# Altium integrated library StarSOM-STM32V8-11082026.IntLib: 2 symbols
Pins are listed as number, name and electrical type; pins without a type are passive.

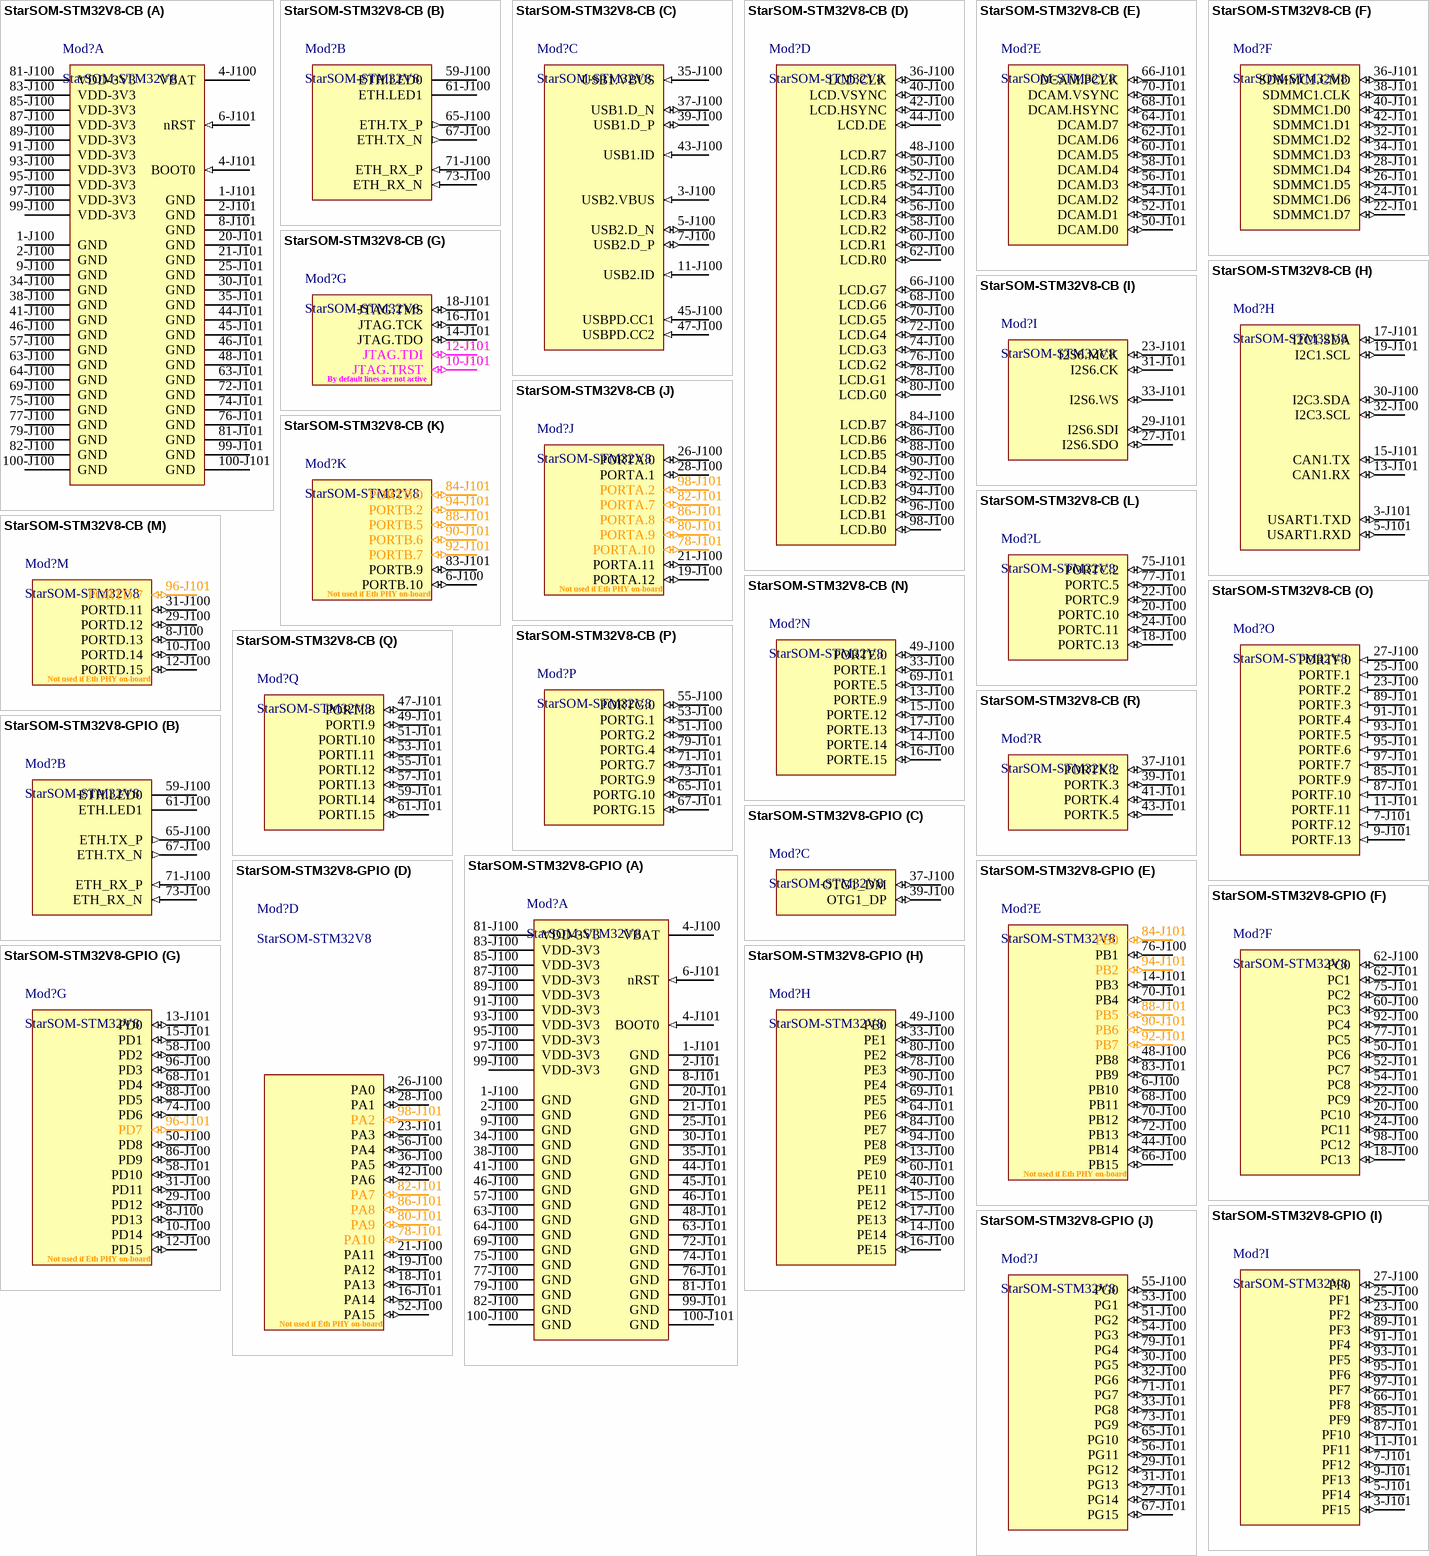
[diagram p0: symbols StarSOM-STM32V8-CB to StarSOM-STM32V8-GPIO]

## StarSOM-STM32V8-CB
designator Mod?, comment StarSOM-STM32V8
StarSOM-STM32V8 schematic model with pins view in functional assignments for peripherals of StarCB-STM32V8-STD
footprint StarSOM-STM32V8 (StarSOM-STM32V8 (SLS08))
part A pins: 1-J100 GND (power), 1-J101 GND (power), 2-J100 GND (power), 2-J101 GND (power), 4-J100 VBAT (power), 4-J101 BOOT0 (in), 6-J101 nRST (in), 8-J101 GND (power), 9-J100 GND (power), 20-J101 GND (power), 21-J101 GND (power), 25-J101 GND (power), 30-J101 GND (power), 34-J100 GND (power), 35-J101 GND (power), 38-J100 GND (power), 41-J100 GND (power), 44-J101 GND (power), 45-J101 GND (power), 46-J100 GND (power), 46-J101 GND (power), 48-J101 GND (power), 57-J100 GND (power), 63-J100 GND (power), 63-J101 GND (power), 64-J100 GND (power), 69-J100 GND (power), 72-J101 GND (power), 74-J101 GND (power), 75-J100 GND (power), 76-J101 GND (power), 77-J100 GND (power), 79-J100 GND (power), 81-J100 VDD-3V3 (power), 81-J101 GND (power), 82-J100 GND (power), 83-J100 VDD-3V3 (power), 85-J100 VDD-3V3 (power), 87-J100 VDD-3V3 (power), 89-J100 VDD-3V3 (power), 91-J100 VDD-3V3 (power), 93-J100 VDD-3V3 (power), 95-J100 VDD-3V3 (power), 97-J100 VDD-3V3 (power), 99-J100 VDD-3V3 (power), 99-J101 GND (power), 100-J100 GND (power), 100-J101 GND (power)
part B pins: 59-J100 ETH.LED0 (oc), 61-J100 ETH.LED1 (oc), 65-J100 ETH.TX_P (out), 67-J100 ETH.TX_N (out), 71-J100 ETH_RX_P (in), 73-J100 ETH_RX_N (in)
part C pins: 3-J100 USB2.VBUS (in), 5-J100 USB2.D_N (io), 7-J100 USB2.D_P (io), 11-J100 USB2.ID (in), 35-J100 USB1.VBUS (in), 37-J100 USB1.D_N (io), 39-J100 USB1.D_P (io), 43-J100 USB1.ID (in), 45-J100 USBPD.CC1 (in), 47-J100 USBPD.CC2 (in)
part D pins: 36-J100 LCD.CLK (io), 40-J100 LCD.VSYNC (io), 42-J100 LCD.HSYNC (io), 44-J100 LCD.DE (io), 48-J100 LCD.R7 (io), 50-J100 LCD.R6 (io), 52-J100 LCD.R5 (io), 54-J100 LCD.R4 (io), 56-J100 LCD.R3 (io), 58-J100 LCD.R2 (io), 60-J100 LCD.R1 (io), 62-J100 LCD.R0 (io), 66-J100 LCD.G7 (io), 68-J100 LCD.G6 (io), 70-J100 LCD.G5 (io), 72-J100 LCD.G4 (io), 74-J100 LCD.G3 (io), 76-J100 LCD.G2 (io), 78-J100 LCD.G1 (io), 80-J100 LCD.G0 (io), 84-J100 LCD.B7 (io), 86-J100 LCD.B6 (io), 88-J100 LCD.B5 (io), 90-J100 LCD.B4 (io), 92-J100 LCD.B3 (io), 94-J100 LCD.B2 (io), 96-J100 LCD.B1 (io), 98-J100 LCD.B0 (io)
part E pins: 50-J101 DCAM.D0 (io), 52-J101 DCAM.D1 (io), 54-J101 DCAM.D2 (io), 56-J101 DCAM.D3 (io), 58-J101 DCAM.D4 (io), 60-J101 DCAM.D5 (io), 62-J101 DCAM.D6 (io), 64-J101 DCAM.D7 (io), 66-J101 DCAM.PCLK (io), 68-J101 DCAM.HSYNC (io), 70-J101 DCAM.VSYNC (io)
part F pins: 22-J101 SDMMC1.D7 (io), 24-J101 SDMMC1.D6 (io), 26-J101 SDMMC1.D5 (io), 28-J101 SDMMC1.D4 (io), 32-J101 SDMMC1.D2 (io), 34-J101 SDMMC1.D3 (io), 36-J101 SDMMC1.CMD (io), 38-J101 SDMMC1.CLK (io), 40-J101 SDMMC1.D0 (io), 42-J101 SDMMC1.D1 (io)
part G pins: 10-J101 JTAG.TRST (io), 12-J101 JTAG.TDI (io), 14-J101 JTAG.TDO (io), 16-J101 JTAG.TCK (io), 18-J101 JTAG.TMS (io)
part H pins: 3-J101 USART1.TXD (io), 5-J101 USART1.RXD (io), 13-J101 CAN1.RX (io), 15-J101 CAN1.TX (io), 17-J101 I2C1.SDA (io), 19-J101 I2C1.SCL (io), 30-J100 I2C3.SDA (io), 32-J100 I2C3.SCL (io)
part I pins: 23-J101 I2S6.MCK (io), 27-J101 I2S6.SDO (io), 29-J101 I2S6.SDI (io), 31-J101 I2S6.CK (io), 33-J101 I2S6.WS (io)
part J pins: 19-J100 PORTA.12 (io), 21-J100 PORTA.11 (io), 26-J100 PORTA.0 (io), 28-J100 PORTA.1 (io), 78-J101 PORTA.10 (io), 80-J101 PORTA.9 (io), 82-J101 PORTA.7 (io), 86-J101 PORTA.8 (io), 98-J101 PORTA.2 (io)
part K pins: 6-J100 PORTB.10 (io), 83-J101 PORTB.9 (io), 84-J101 PORTB.0 (io), 88-J101 PORTB.5 (io), 90-J101 PORTB.6 (io), 92-J101 PORTB.7 (io), 94-J101 PORTB.2 (io)
part L pins: 18-J100 PORTC.13 (io), 20-J100 PORTC.10 (io), 22-J100 PORTC.9 (io), 24-J100 PORTC.11 (io), 75-J101 PORTC.2 (io), 77-J101 PORTC.5 (io)
part M pins: 8-J100 PORTD.13 (io), 10-J100 PORTD.14 (io), 12-J100 PORTD.15 (io), 29-J100 PORTD.12 (io), 31-J100 PORTD.11 (io), 96-J101 PORTD.7 (io)
part N pins: 13-J100 PORTE.9 (io), 14-J100 PORTE.14 (io), 15-J100 PORTE.12 (io), 16-J100 PORTE.15 (io), 17-J100 PORTE.13 (io), 33-J100 PORTE.1 (io), 49-J100 PORTE.0 (io), 69-J101 PORTE.5 (io)
part O pins: 7-J101 PORTF.12 (in), 9-J101 PORTF.13 (in), 11-J101 PORTF.11 (in), 23-J100 PORTF.2 (in), 25-J100 PORTF.1 (in), 27-J100 PORTF.0 (in), 85-J101 PORTF.9 (in), 87-J101 PORTF.10 (in), 89-J101 PORTF.3 (in), 91-J101 PORTF.4 (in), 93-J101 PORTF.5 (in), 95-J101 PORTF.6 (in), 97-J101 PORTF.7 (in)
part P pins: 51-J100 PORTG.2 (io), 53-J100 PORTG.1 (io), 55-J100 PORTG.0 (io), 65-J101 PORTG.10 (io), 67-J101 PORTG.15 (io), 71-J101 PORTG.7 (io), 73-J101 PORTG.9 (io), 79-J101 PORTG.4 (io)
part Q pins: 47-J101 PORTI.8 (io), 49-J101 PORTI.9 (io), 51-J101 PORTI.10 (io), 53-J101 PORTI.11 (io), 55-J101 PORTI.12 (io), 57-J101 PORTI.13 (io), 59-J101 PORTI.14 (io), 61-J101 PORTI.15 (io)
part R pins: 37-J101 PORTK.2 (io), 39-J101 PORTK.3 (io), 41-J101 PORTK.4 (io), 43-J101 PORTK.5 (io)

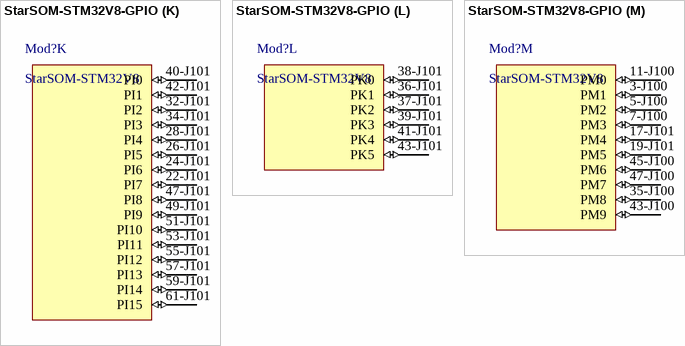
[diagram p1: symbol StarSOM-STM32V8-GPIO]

## StarSOM-STM32V8-GPIO
designator Mod?, comment StarSOM-STM32V8
StarSOM-STM32V8 schematic model with pins view in GPIO mode
footprint StarSOM-STM32V8 (StarSOM-STM32V8 (SLS08))
part A pins: 1-J100 GND (power), 1-J101 GND (power), 2-J100 GND (power), 2-J101 GND (power), 4-J100 VBAT (power), 4-J101 BOOT0 (in), 6-J101 nRST (in), 8-J101 GND (power), 9-J100 GND (power), 20-J101 GND (power), 21-J101 GND (power), 25-J101 GND (power), 30-J101 GND (power), 34-J100 GND (power), 35-J101 GND (power), 38-J100 GND (power), 41-J100 GND (power), 44-J101 GND (power), 45-J101 GND (power), 46-J100 GND (power), 46-J101 GND (power), 48-J101 GND (power), 57-J100 GND (power), 63-J100 GND (power), 63-J101 GND (power), 64-J100 GND (power), 69-J100 GND (power), 72-J101 GND (power), 74-J101 GND (power), 75-J100 GND (power), 76-J101 GND (power), 77-J100 GND (power), 79-J100 GND (power), 81-J100 VDD-3V3 (power), 81-J101 GND (power), 82-J100 GND (power), 83-J100 VDD-3V3 (power), 85-J100 VDD-3V3 (power), 87-J100 VDD-3V3 (power), 89-J100 VDD-3V3 (power), 91-J100 VDD-3V3 (power), 93-J100 VDD-3V3 (power), 95-J100 VDD-3V3 (power), 97-J100 VDD-3V3 (power), 99-J100 VDD-3V3 (power), 99-J101 GND (power), 100-J100 GND (power), 100-J101 GND (power)
part B pins: 59-J100 ETH.LED0 (oc), 61-J100 ETH.LED1 (oc), 65-J100 ETH.TX_P (out), 67-J100 ETH.TX_N (out), 71-J100 ETH_RX_P (in), 73-J100 ETH_RX_N (in)
part C pins: 37-J100 OTG1_DM (io), 39-J100 OTG1_DP (io)
part D pins: 16-J101 PA14 (io), 18-J101 PA13 (io), 19-J100 PA12 (io), 21-J100 PA11 (io), 23-J101 PA3 (io), 26-J100 PA0 (io), 28-J100 PA1 (io), 36-J100 PA5 (io), 42-J100 PA6 (io), 52-J100 PA15 (io), 56-J100 PA4 (io), 78-J101 PA10 (io), 80-J101 PA9 (io), 82-J101 PA7 (io), 86-J101 PA8 (io), 98-J101 PA2 (io)
part E pins: 6-J100 PB10 (io), 14-J101 PB3 (io), 44-J100 PB14 (io), 48-J100 PB8 (io), 66-J100 PB15 (io), 68-J100 PB11 (io), 70-J100 PB12 (io), 70-J101 PB4 (io), 72-J100 PB13 (io), 76-J100 PB1 (io), 83-J101 PB9 (io), 84-J101 PB0 (io), 88-J101 PB5 (io), 90-J101 PB6 (io), 92-J101 PB7 (io), 94-J101 PB2 (io)
part F pins: 18-J100 PC13 (io), 20-J100 PC10 (io), 22-J100 PC9 (io), 24-J100 PC11 (io), 50-J101 PC6 (io), 52-J101 PC7 (io), 54-J101 PC8 (io), 60-J100 PC3 (io), 62-J100 PC0 (io), 62-J101 PC1 (io), 75-J101 PC2 (io), 77-J101 PC5 (io), 92-J100 PC4 (io), 98-J100 PC12 (io)
part G pins: 8-J100 PD13 (io), 10-J100 PD14 (io), 12-J100 PD15 (io), 13-J101 PD0 (io), 15-J101 PD1 (io), 29-J100 PD12 (io), 31-J100 PD11 (io), 50-J100 PD8 (io), 58-J100 PD2 (io), 58-J101 PD10 (io), 68-J101 PD4 (io), 74-J100 PD6 (io), 86-J100 PD9 (io), 88-J100 PD5 (io), 96-J100 PD3 (io), 96-J101 PD7 (io)
part H pins: 13-J100 PE9 (io), 14-J100 PE14 (io), 15-J100 PE12 (io), 16-J100 PE15 (io), 17-J100 PE13 (io), 33-J100 PE1 (io), 40-J100 PE11 (io), 49-J100 PE0 (io), 60-J101 PE10 (io), 64-J101 PE6 (io), 69-J101 PE5 (io), 78-J100 PE3 (io), 80-J100 PE2 (io), 84-J100 PE7 (io), 90-J100 PE4 (io), 94-J100 PE8 (io)
part I pins: 3-J101 PF15 (io), 5-J101 PF14 (io), 7-J101 PF12 (io), 9-J101 PF13 (io), 11-J101 PF11 (io), 23-J100 PF2 (io), 25-J100 PF1 (io), 27-J100 PF0 (io), 66-J101 PF8 (io), 85-J101 PF9 (io), 87-J101 PF10 (io), 89-J101 PF3 (io), 91-J101 PF4 (io), 93-J101 PF5 (io), 95-J101 PF6 (io), 97-J101 PF7 (io)
part J pins: 27-J101 PG14 (io), 29-J101 PG12 (io), 30-J100 PG5 (io), 31-J101 PG13 (io), 32-J100 PG6 (io), 33-J101 PG8 (io), 51-J100 PG2 (io), 53-J100 PG1 (io), 54-J100 PG3 (io), 55-J100 PG0 (io), 56-J101 PG11 (io), 65-J101 PG10 (io), 67-J101 PG15 (io), 71-J101 PG7 (io), 73-J101 PG9 (io), 79-J101 PG4 (io)
part K pins: 22-J101 PI7 (io), 24-J101 PI6 (io), 26-J101 PI5 (io), 28-J101 PI4 (io), 32-J101 PI2 (io), 34-J101 PI3 (io), 40-J101 PI0 (io), 42-J101 PI1 (io), 47-J101 PI8 (io), 49-J101 PI9 (io), 51-J101 PI10 (io), 53-J101 PI11 (io), 55-J101 PI12 (io), 57-J101 PI13 (io), 59-J101 PI14 (io), 61-J101 PI15 (io)
part L pins: 36-J101 PK1 (io), 37-J101 PK2 (io), 38-J101 PK0 (io), 39-J101 PK3 (io), 41-J101 PK4 (io), 43-J101 PK5 (io)
part M pins: 3-J100 PM1 (io), 5-J100 PM2 (io), 7-J100 PM3 (io), 11-J100 PM0 (io), 17-J101 PM4 (io), 19-J101 PM5 (io), 35-J100 PM8 (io), 43-J100 PM9 (io), 45-J100 PM6 (io), 47-J100 PM7 (io)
